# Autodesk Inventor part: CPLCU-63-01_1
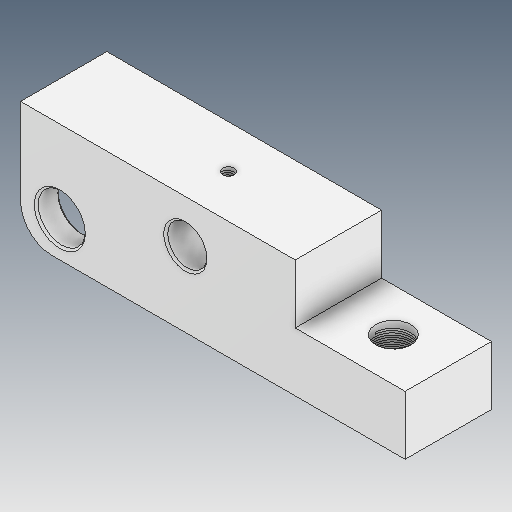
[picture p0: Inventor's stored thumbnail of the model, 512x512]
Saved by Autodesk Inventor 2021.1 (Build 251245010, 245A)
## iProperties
Created: 2021-06
Part Number: CPLCU-63-01_1
Material: Ogólny
Document SubType Name: Modeling
Designer: user
Density: 1 g/cm^3
Appearance: Domyślna
Author: user
Revision Number: ÈÎºÎ
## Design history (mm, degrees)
feature "ÊäÈë1"
node "Bryła1"
